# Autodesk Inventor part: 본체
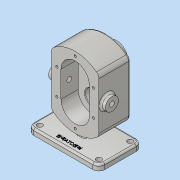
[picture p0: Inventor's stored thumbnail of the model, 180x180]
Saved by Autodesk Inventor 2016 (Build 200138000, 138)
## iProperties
Created: 2019-03
Part Number: 본체
Material: 알루미늄 6061
Document SubType Name: Modeling
Designer: Administrator
Density: 2.7 g/cm^3
Appearance: 알루미늄 - 평지
Mass: 1187.16 g
Surface Area: 719.273 cm^2
Volume: 439.69 cm^3
Author: Administrator
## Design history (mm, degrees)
sketch "스케치1"
  geometry: L1 (40, 122.721)-(-40, 122.721); L2 (-40, 122.721)-(-40, 33.279); L3 (-40, 33.279)-(40, 33.279); L4 (40, 33.279)-(40, 122.721); L5 (40, 78)-(-40, 78); A1 r 60 centre (0, 78) between (40, 122.721) and (-40, 122.721); A2 r 60 centre (0, 78) between (-40, 33.279) and (40, 33.279); 2 further points
  constraints: 10 end point, 4 point on circle, 3 midpoint, 2 centre point, 2 parallel, 1 horizontal, 1 perpendicular, 1 vertical alignment
  dimensions: "d0" = 80 distance of L3.end L2.end; "d2" = 60 radius of A1; "d3" = 60 radius of A2; "d4" = 78 distance from line of point (0, 0) L5; "d5" = 78 distance of point (0, 0) A1.centre
extrude "돌출1" new body sketch "스케치1" distance "d6" = 53; taper "d7" = 0 deg
sketch "스케치2"
  geometry: L1 (60, -10)-(-60, -10); L2 (-60, -10)-(-60, 0); L3 (-60, 0)-(60, 0); L4 (60, 0)-(60, -10); 2 further points
  constraints: 8 end point, 2 parallel, 1 coincident, 1 horizontal, 1 midpoint, 1 perpendicular
  dimensions: "d8" = 10 distance of L1.end L2.end; "d9" = 120 distance of L1.start L1.end
extrude "돌출2" join sketch "스케치2" distance "d10" = 73; taper "d11" = 0 deg
sketch "스케치3"
  geometry: L1 (6, 28.92)-(-6, 28.92); L2 (-6, 0)-(-6, -28.92); L3 (-6, -28.92)-(6, -28.92); L4 (6, -28.92)-(6, 0); L5 (6, 28.92)-(-6, -28.92); L6 (-6, 28.92)-(6, -28.92); L7 (-60, 0)-(60, 0) reference; L8 (6, 0)-(-6, 0); 1 further point
  constraints: 14 end point, 2 horizontal, 2 midpoint, 2 parallel, 2 point on line, 1 perpendicular
  dimensions: "d12" = 12 distance of L3.end L2.end
extrude "돌출3" join sketch "스케치3" distance "d13" = 43; taper "d14" = 0 deg
sketch "스케치4"
  geometry: L1 (-60, 0)-(60, 0) reference; L2 (-24, 100)-(-24, 56); L3 (24, 100)-(24, 56); A1 r 60 centre (0, 78) between (-40, 33.279) and (40, 33.279) reference; A2 r 24 centre (0, 100) between (24, 100) and (-24, 100); A3 r 24 centre (0, 56) between (-24, 56) and (24, 56); 2 further points
  constraints: 4 end point, 4 point on circle, 2 centre point, 2 tangent, 2 vertical, 2 vertical alignment, 1 midpoint
  dimensions: "d15" = 24 radius of A2; "d16" = 24 radius of A3; "d17" = 44 distance of A3.centre A2.centre; "d18" = 22 distance of A2.centre A1.centre
extrude "돌출4" cut sketch "스케치4" distance "d19" = 29; taper "d20" = 0 deg
sketch "스케치5"
  geometry: L1 (-60, 0)-(60, 0) reference; C1 r 19 at (0, -100); 2 further points
  constraints: 1 centre point, 1 midpoint, 1 vertical alignment
  dimensions: "d21" = 38 diameter of C1; "d22" = 100 distance of point (0, 0) C1.centre
extrude "돌출5" join sketch "스케치5" distance "d23" = 17; taper "d24" = 0 deg
hole "구멍1" diameter "d27" = 17; stored, may be unused: countersink angle "d31" = 90 deg, drill point angle "d33" = 118 deg; dims "d25" = 10, "d26" = 10, "d28" = 6, "d29" = 28, "d30" = 7.3, "d32" = 8
sketch "스케치6"
  geometry: A1 r 24 centre (0, 100) between (24, 100) and (-24, 100) reference; A2 r 24 centre (0, 56) between (-24, 56) and (24, 56) reference; 3 further points
  constraints: 2 coincident
hole "구멍2" sketch "스케치6" at (0, 100), (0, 56) diameter "d34" = 25; stored, may be unused: countersink angle "d38" = 90 deg, drill point angle "d40" = 0 deg; dims "d35" = 6, "d36" = 28, "d37" = 7.3, "d39" = 15
sketch "스케치7"
  geometry: L1 (0, 100)-(0, 131); C1 r 19 at (0, 100) reference; 2 further points
  constraints: 2 end point, 1 coincident, 1 vertical
  dimensions: "d41" = 31 distance of L1.start L1.end
hole "구멍3" sketch "스케치7" at (0, 131) diameter "d42" = 4.134; stored, may be unused: countersink angle "d46" = 90 deg, drill point angle "d48" = 118 deg; dims "d43" = 10, "d44" = 28, "d45" = 7.3, "d47" = 12
node "작업 평면1"
sketch "스케치8"
  geometry: L1 (89.443, -53)-(0, -53) reference; L2 (122.721, 0)-(122.721, -73) reference; C1 r 11 at (44.721, -39)
  constraints: 1 centre point
  dimensions: "d53" = 22 diameter of C1; "d54" = 78 distance from line of L2 C1.centre; "d55" = 14 distance from line of L1 C1.centre
extrude "돌출6" join sketch "스케치8" distance "d56" = 8; taper "d57" = 0 deg
hole "구멍4" diameter "d60" = 8.376; stored, may be unused: countersink angle "d64" = 90 deg, drill point angle "d66" = 118 deg; dims "d58" = 10, "d59" = 10, "d61" = 20, "d62" = 28, "d63" = 7.3, "d65" = 27.3
fillet "모깎기1" dims "d67" = 10
sketch "스케치9"
  geometry: A1 r 10 centre (-44, 33) between (-44, 43) and (-54, 33) reference; A2 r 10 centre (-44, -20) between (-54, -20) and (-44, -30) reference; A3 r 10 centre (56, -20) between (56, -30) and (66, -20) reference; A4 r 10 centre (56, 33) between (66, 33) and (56, 43) reference; 5 further points
  constraints: 4 coincident
hole "구멍5" sketch "스케치9" at (-44, -20), (-44, 33), (56, -20), (56, 33) diameter "d68" = 9; stored, may be unused: countersink angle "d72" = 90 deg, drill point angle "d74" = 118 deg; dims "d69" = 20, "d70" = 28, "d71" = 7.3, "d73" = 27.3
sketch "스케치10"
  geometry: L1 (-54, 33)-(-54, -20) reference; L2 (56, -30)-(-44, -30) reference; 2 further points
  constraints: 1 other
  dimensions: "d75" = 60 distance from line of point (6, -20) L1; "d76" = 10 distance from line of L2 point (6, -20)
feature "엠보싱1" sketch "스케치10" dims "d0" = 80, "d2" = 60, "d3" = 60, "d4" = 78, "d5" = 78, "d77" = 0.5, "d78" = 0
fillet "모깎기3" dims "d80" = 3
chamfer "모따기1" distance "d81" = 1; stored, may be unused: second distance "d82" = 2, angle "d83" = 45 deg
fillet "모깎기4" dims "d84" = 0.5
chamfer "모따기2" distance "d85" = 0.7; stored, may be unused: second distance "d86" = 2, angle "d87" = 30 deg
fillet "모깎기5" dims "d88" = 10
fillet "모깎기10" dims "d93" = 3
fillet "모깎기8" dims "d91" = 3
fillet "모깎기9" dims "d92" = 3
node "솔리드1"
pattern_circular "원형 패턴1" dims angle "d50" = 180 deg
mirror "대칭1"
mirror "대칭2"
other parameters: "d52" = 78
